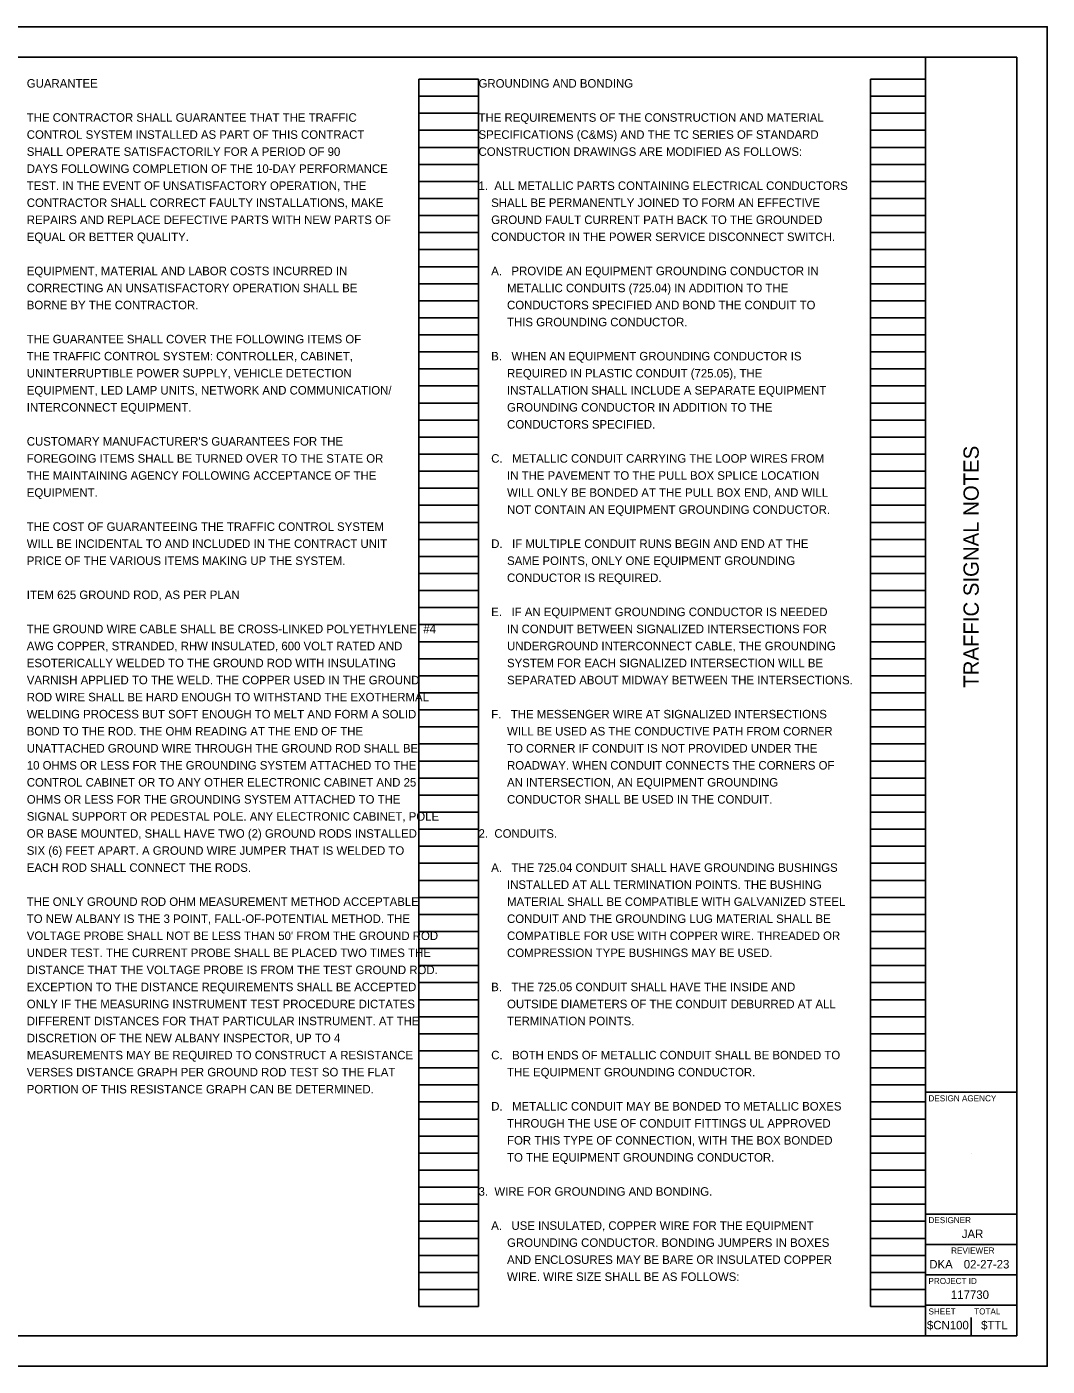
# Model space of a CAD drawing. Extents: x 0 to 34, y 0 to 22.
# Drawn here: x 17.24 to 34, y 0 to 22 of the extents above; entities that cross this region are included whole.
import ezdxf

# ---------------------------------------------------------------- set-up
doc = ezdxf.new("R2010")
doc.units = 0
for name, color, linetype in [('SH_Border', 7, 'Continuous'), ('SH_Cut_Line', 7, 'Continuous'), ('SH_Data', 7, 'Continuous'), ('SH_Text', 7, 'Continuous')]:
    doc.layers.add(name, color=color, linetype=linetype)

msp = doc.modelspace()

# ---------------------------------------------------------------- linework, layer by layer
at = {"layer": 'SH_Border'}
for p, q in [((32, 0.5), (32, 21.5)), ((32, 4.5), (33.5, 4.5)), ((32, 2.5), (33.5, 2.5)), ((32, 2), (33.5, 2)), ((32, 1.5), (33.5, 1.5)), ((32, 1), (33.5, 1))]:
    msp.add_line(p, q, dxfattribs=at)
msp.add_lwpolyline([(1.5, 21.5), (33.5, 21.5), (33.5, 0.5), (1.5, 0.5)], close=True, dxfattribs=at)
at = {"layer": 'SH_Cut_Line'}
msp.add_lwpolyline([(0, 0), (34, 0), (34, 22), (0, 22)], close=True, dxfattribs=at)
at = {"layer": 'SH_Data'}
for p, q in [((23.68, 0.98), (23.68, 21.14)), ((23.68, 21.14), (24.66, 21.14)), ((24.66, 0.98), (24.66, 21.14)), ((31.1, 0.98), (31.1, 21.14)), ((31.1, 21.14), (32, 21.14)), ((32, 0.98), (32, 21.14)), ((23.68, 20.86), (24.66, 20.86)), ((31.1, 20.86), (32, 20.86)), ((23.68, 20.58), (24.66, 20.58)), ((31.1, 20.58), (32, 20.58)), ((23.68, 20.3), (24.66, 20.3)), ((31.1, 20.3), (32, 20.3)), ((23.68, 20.02), (24.66, 20.02)), ((31.1, 20.02), (32, 20.02)), ((23.68, 19.74), (24.66, 19.74)), ((31.1, 19.74), (32, 19.74)), ((23.68, 19.46), (24.66, 19.46)), ((31.1, 19.46), (32, 19.46)), ((23.68, 19.18), (24.66, 19.18)), ((31.1, 19.18), (32, 19.18)), ((23.68, 18.9), (24.66, 18.9)), ((31.1, 18.9), (32, 18.9)), ((23.68, 18.62), (24.66, 18.62)), ((31.1, 18.62), (32, 18.62)), ((23.68, 18.34), (24.66, 18.34)), ((31.1, 18.34), (32, 18.34)), ((23.68, 18.06), (24.66, 18.06)), ((31.1, 18.06), (32, 18.06)), ((23.68, 17.78), (24.66, 17.78)), ((31.1, 17.78), (32, 17.78)), ((23.68, 17.5), (24.66, 17.5)), ((31.1, 17.5), (32, 17.5)), ((23.68, 17.22), (24.66, 17.22)), ((31.1, 17.22), (32, 17.22)), ((23.68, 16.94), (24.66, 16.94)), ((31.1, 16.94), (32, 16.94)), ((23.68, 16.66), (24.66, 16.66)), ((31.1, 16.66), (32, 16.66)), ((23.68, 16.38), (24.66, 16.38)), ((31.1, 16.38), (32, 16.38)), ((23.68, 16.1), (24.66, 16.1)), ((31.1, 16.1), (32, 16.1)), ((23.68, 15.82), (24.66, 15.82)), ((31.1, 15.82), (32, 15.82)), ((23.68, 15.54), (24.66, 15.54)), ((31.1, 15.54), (32, 15.54)), ((23.68, 15.26), (24.66, 15.26)), ((31.1, 15.26), (32, 15.26)), ((23.68, 14.98), (24.66, 14.98)), ((31.1, 14.98), (32, 14.98)), ((23.68, 14.7), (24.66, 14.7)), ((31.1, 14.7), (32, 14.7)), ((23.68, 14.42), (24.66, 14.42)), ((31.1, 14.42), (32, 14.42)), ((23.68, 14.14), (24.66, 14.14)), ((31.1, 14.14), (32, 14.14)), ((23.68, 13.86), (24.66, 13.86)), ((31.1, 13.86), (32, 13.86)), ((23.68, 13.58), (24.66, 13.58)), ((31.1, 13.58), (32, 13.58)), ((23.68, 13.3), (24.66, 13.3)), ((31.1, 13.3), (32, 13.3)), ((23.68, 13.02), (24.66, 13.02)), ((31.1, 13.02), (32, 13.02)), ((23.68, 12.74), (24.66, 12.74)), ((31.1, 12.74), (32, 12.74)), ((23.68, 12.46), (24.66, 12.46)), ((31.1, 12.46), (32, 12.46)), ((23.68, 12.18), (24.66, 12.18)), ((31.1, 12.18), (32, 12.18)), ((23.68, 11.9), (24.66, 11.9)), ((31.1, 11.9), (32, 11.9)), ((23.68, 11.62), (24.66, 11.62)), ((31.1, 11.62), (32, 11.62)), ((23.68, 11.34), (24.66, 11.34)), ((31.1, 11.34), (32, 11.34)), ((23.68, 11.06), (24.66, 11.06)), ((31.1, 11.06), (32, 11.06)), ((23.68, 10.78), (24.66, 10.78)), ((31.1, 10.78), (32, 10.78)), ((23.68, 10.5), (24.66, 10.5)), ((31.1, 10.5), (32, 10.5)), ((23.68, 10.22), (24.66, 10.22)), ((31.1, 10.22), (32, 10.22)), ((23.68, 9.94), (24.66, 9.94)), ((31.1, 9.94), (32, 9.94)), ((23.68, 9.66), (24.66, 9.66)), ((31.1, 9.66), (32, 9.66)), ((23.68, 9.38), (24.66, 9.38)), ((31.1, 9.38), (32, 9.38)), ((23.68, 9.1), (24.66, 9.1)), ((31.1, 9.1), (32, 9.1)), ((23.68, 8.82), (24.66, 8.82)), ((31.1, 8.82), (32, 8.82)), ((23.68, 8.54), (24.66, 8.54)), ((31.1, 8.54), (32, 8.54)), ((23.68, 8.26), (24.66, 8.26)), ((31.1, 8.26), (32, 8.26)), ((23.68, 7.98), (24.66, 7.98)), ((31.1, 7.98), (32, 7.98)), ((23.68, 7.7), (24.66, 7.7)), ((31.1, 7.7), (32, 7.7)), ((23.68, 7.42), (24.66, 7.42)), ((31.1, 7.42), (32, 7.42)), ((23.68, 7.14), (24.66, 7.14)), ((31.1, 7.14), (32, 7.14)), ((23.68, 6.86), (24.66, 6.86)), ((31.1, 6.86), (32, 6.86)), ((23.68, 6.58), (24.66, 6.58)), ((31.1, 6.58), (32, 6.58)), ((23.68, 6.3), (24.66, 6.3)), ((31.1, 6.3), (32, 6.3)), ((23.68, 6.02), (24.66, 6.02)), ((31.1, 6.02), (32, 6.02)), ((23.68, 5.74), (24.66, 5.74)), ((31.1, 5.74), (32, 5.74)), ((23.68, 5.46), (24.66, 5.46)), ((31.1, 5.46), (32, 5.46)), ((23.68, 5.18), (24.66, 5.18)), ((31.1, 5.18), (32, 5.18)), ((23.68, 4.9), (24.66, 4.9)), ((31.1, 4.9), (32, 4.9)), ((23.68, 4.62), (24.66, 4.62)), ((31.1, 4.62), (32, 4.62)), ((23.68, 4.34), (24.66, 4.34)), ((31.1, 4.34), (32, 4.34)), ((23.68, 4.06), (24.66, 4.06)), ((31.1, 4.06), (32, 4.06)), ((23.68, 3.78), (24.66, 3.78)), ((31.1, 3.78), (32, 3.78)), ((23.68, 3.5), (24.66, 3.5)), ((31.1, 3.5), (32, 3.5)), ((32.75, 3.5), (32.75, 3.5)), ((23.68, 3.22), (24.66, 3.22)), ((31.1, 3.22), (32, 3.22)), ((23.68, 2.94), (24.66, 2.94)), ((31.1, 2.94), (32, 2.94)), ((23.68, 2.66), (24.66, 2.66)), ((31.1, 2.66), (32, 2.66)), ((23.68, 2.38), (24.66, 2.38)), ((31.1, 2.38), (32, 2.38)), ((23.68, 2.1), (24.66, 2.1)), ((31.1, 2.1), (32, 2.1)), ((23.68, 1.82), (24.66, 1.82)), ((31.1, 1.82), (32, 1.82)), ((23.68, 1.54), (24.66, 1.54)), ((31.1, 1.54), (32, 1.54)), ((23.68, 1.26), (24.66, 1.26)), ((31.1, 1.26), (32, 1.26)), ((23.68, 0.98), (24.66, 0.98)), ((31.1, 0.98), (32, 0.98)), ((32.375, 0.675), (32.375, 0.675)), ((32.75, 0.5), (32.75, 0.8))]:
    msp.add_line(p, q, dxfattribs=at)

# ---------------------------------------------------------------- texts
msp.add_text('TRAFFIC SIGNAL NOTES', height=0.25, rotation=90, dxfattribs=at).set_placement((32.875, 11.144))
for s, height, p in [('DESIGN AGENCY', 0.1, (32.05, 4.35)), ('DESIGNER', 0.1, (32.05, 2.35)), ('JAR', 0.14, (32.597, 2.105)), ('REVIEWER', 0.1, (32.422, 1.85)), ('DKA', 0.14, (32.063, 1.605)), ('02-27-23', 0.14, (32.629, 1.605)), ('PROJECT ID', 0.1, (32.05, 1.35)), ('117730', 0.14, (32.419, 1.105)), ('SHEET', 0.1, (32.05, 0.85)), ('TOTAL', 0.1, (32.8, 0.85)), ('$CN100', 0.14, (32.025, 0.605)), ('$TTL', 0.14, (32.915, 0.605))]:
    msp.add_text(s, height=height, dxfattribs=at).set_placement(p)
at = {"layer": 'SH_Text'}
for s, p in [('GUARANTEE', (17.24, 21)), ('GROUNDING AND BONDING', (24.66, 21)), ('THE CONTRACTOR SHALL GUARANTEE THAT THE TRAFFIC', (17.24, 20.44)), ('THE REQUIREMENTS OF THE CONSTRUCTION AND MATERIAL', (24.66, 20.44)), ('CONTROL SYSTEM INSTALLED AS PART OF THIS CONTRACT', (17.24, 20.16)), ('SPECIFICATIONS (C&MS) AND THE TC SERIES OF STANDARD', (24.66, 20.16)), ('SHALL OPERATE SATISFACTORILY FOR A PERIOD OF 90', (17.24, 19.88)), ('CONSTRUCTION DRAWINGS ARE MODIFIED AS FOLLOWS:', (24.66, 19.88)), ('DAYS FOLLOWING COMPLETION OF THE 10-DAY PERFORMANCE', (17.24, 19.6)), ('TEST. IN THE EVENT OF UNSATISFACTORY OPERATION, THE', (17.24, 19.32)), ('1.  ALL METALLIC PARTS CONTAINING ELECTRICAL CONDUCTORS', (24.66, 19.32)), ('CONTRACTOR SHALL CORRECT FAULTY INSTALLATIONS, MAKE', (17.24, 19.04)), ('    SHALL BE PERMANENTLY JOINED TO FORM AN EFFECTIVE', (24.66, 19.04)), ('REPAIRS AND REPLACE DEFECTIVE PARTS WITH NEW PARTS OF', (17.24, 18.76)), ('    GROUND FAULT CURRENT PATH BACK TO THE GROUNDED', (24.66, 18.76)), ('EQUAL OR BETTER QUALITY.', (17.24, 18.48)), ('    CONDUCTOR IN THE POWER SERVICE DISCONNECT SWITCH.', (24.66, 18.48)), ('EQUIPMENT, MATERIAL AND LABOR COSTS INCURRED IN', (17.24, 17.92)), ('    A.   PROVIDE AN EQUIPMENT GROUNDING CONDUCTOR IN', (24.66, 17.92)), ('CORRECTING AN UNSATISFACTORY OPERATION SHALL BE', (17.24, 17.64)), ('         METALLIC CONDUITS (725.04) IN ADDITION TO THE', (24.66, 17.64)), ('BORNE BY THE CONTRACTOR.', (17.24, 17.36)), ('         CONDUCTORS SPECIFIED AND BOND THE CONDUIT TO', (24.66, 17.36)), ('         THIS GROUNDING CONDUCTOR.', (24.66, 17.08)), ('THE GUARANTEE SHALL COVER THE FOLLOWING ITEMS OF', (17.24, 16.8)), ('THE TRAFFIC CONTROL SYSTEM: CONTROLLER, CABINET,', (17.24, 16.52)), ('    B.   WHEN AN EQUIPMENT GROUNDING CONDUCTOR IS', (24.66, 16.52)), ('UNINTERRUPTIBLE POWER SUPPLY, VEHICLE DETECTION', (17.24, 16.24)), ('         REQUIRED IN PLASTIC CONDUIT (725.05), THE', (24.66, 16.24)), ('EQUIPMENT, LED LAMP UNITS, NETWORK AND COMMUNICATION/', (17.24, 15.96)), ('         INSTALLATION SHALL INCLUDE A SEPARATE EQUIPMENT', (24.66, 15.96)), ('INTERCONNECT EQUIPMENT.', (17.24, 15.68)), ('         GROUNDING CONDUCTOR IN ADDITION TO THE', (24.66, 15.68)), ('         CONDUCTORS SPECIFIED.', (24.66, 15.4)), ("CUSTOMARY MANUFACTURER'S GUARANTEES FOR THE", (17.24, 15.12)), ('FOREGOING ITEMS SHALL BE TURNED OVER TO THE STATE OR', (17.24, 14.84)), ('    C.   METALLIC CONDUIT CARRYING THE LOOP WIRES FROM', (24.66, 14.84)), ('THE MAINTAINING AGENCY FOLLOWING ACCEPTANCE OF THE', (17.24, 14.56)), ('         IN THE PAVEMENT TO THE PULL BOX SPLICE LOCATION', (24.66, 14.56)), ('EQUIPMENT.', (17.24, 14.28)), ('         WILL ONLY BE BONDED AT THE PULL BOX END, AND WILL', (24.66, 14.28)), ('         NOT CONTAIN AN EQUIPMENT GROUNDING CONDUCTOR.', (24.66, 14)), ('THE COST OF GUARANTEEING THE TRAFFIC CONTROL SYSTEM', (17.24, 13.72)), ('WILL BE INCIDENTAL TO AND INCLUDED IN THE CONTRACT UNIT', (17.24, 13.44)), ('    D.   IF MULTIPLE CONDUIT RUNS BEGIN AND END AT THE', (24.66, 13.44)), ('PRICE OF THE VARIOUS ITEMS MAKING UP THE SYSTEM.', (17.24, 13.16)), ('         SAME POINTS, ONLY ONE EQUIPMENT GROUNDING', (24.66, 13.16)), ('         CONDUCTOR IS REQUIRED.', (24.66, 12.88)), ('ITEM 625 GROUND ROD, AS PER PLAN', (17.24, 12.6)), ('    E.   IF AN EQUIPMENT GROUNDING CONDUCTOR IS NEEDED', (24.66, 12.32)), ('THE GROUND WIRE CABLE SHALL BE CROSS-LINKED POLYETHYLENE, #4 ', (17.24, 12.04)), ('         IN CONDUIT BETWEEN SIGNALIZED INTERSECTIONS FOR', (24.66, 12.04)), ('AWG COPPER, STRANDED, RHW INSULATED, 600 VOLT RATED AND ', (17.24, 11.76)), ('         UNDERGROUND INTERCONNECT CABLE, THE GROUNDING', (24.66, 11.76)), ('ESOTERICALLY WELDED TO THE GROUND ROD WITH INSULATING ', (17.24, 11.48)), ('         SYSTEM FOR EACH SIGNALIZED INTERSECTION WILL BE', (24.66, 11.48)), ('VARNISH APPLIED TO THE WELD. THE COPPER USED IN THE GROUND ', (17.24, 11.2)), ('         SEPARATED ABOUT MIDWAY BETWEEN THE INTERSECTIONS.', (24.66, 11.2)), ('ROD WIRE SHALL BE HARD ENOUGH TO WITHSTAND THE EXOTHERMAL ', (17.24, 10.92)), ('WELDING PROCESS BUT SOFT ENOUGH TO MELT AND FORM A SOLID ', (17.24, 10.64)), ('    F.   THE MESSENGER WIRE AT SIGNALIZED INTERSECTIONS', (24.66, 10.64)), ('BOND TO THE ROD. THE OHM READING AT THE END OF THE ', (17.24, 10.36)), ('         WILL BE USED AS THE CONDUCTIVE PATH FROM CORNER', (24.66, 10.36)), ('UNATTACHED GROUND WIRE THROUGH THE GROUND ROD SHALL BE ', (17.24, 10.08)), ('         TO CORNER IF CONDUIT IS NOT PROVIDED UNDER THE', (24.66, 10.08)), ('10 OHMS OR LESS FOR THE GROUNDING SYSTEM ATTACHED TO THE ', (17.24, 9.8)), ('         ROADWAY. WHEN CONDUIT CONNECTS THE CORNERS OF', (24.66, 9.8)), ('CONTROL CABINET OR TO ANY OTHER ELECTRONIC CABINET AND 25 ', (17.24, 9.52)), ('         AN INTERSECTION, AN EQUIPMENT GROUNDING', (24.66, 9.52)), ('OHMS OR LESS FOR THE GROUNDING SYSTEM ATTACHED TO THE ', (17.24, 9.24)), ('         CONDUCTOR SHALL BE USED IN THE CONDUIT.', (24.66, 9.24)), ('SIGNAL SUPPORT OR PEDESTAL POLE. ANY ELECTRONIC CABINET, POLE ', (17.24, 8.96)), ('OR BASE MOUNTED, SHALL HAVE TWO (2) GROUND RODS INSTALLED ', (17.24, 8.68)), ('2.  CONDUITS.', (24.66, 8.68)), ('SIX (6) FEET APART. A GROUND WIRE JUMPER THAT IS WELDED TO ', (17.24, 8.4)), ('EACH ROD SHALL CONNECT THE RODS.', (17.24, 8.12)), ('    A.   THE 725.04 CONDUIT SHALL HAVE GROUNDING BUSHINGS', (24.66, 8.12)), ('         INSTALLED AT ALL TERMINATION POINTS. THE BUSHING', (24.66, 7.84)), ('THE ONLY GROUND ROD OHM MEASUREMENT METHOD ACCEPTABLE ', (17.24, 7.56)), ('         MATERIAL SHALL BE COMPATIBLE WITH GALVANIZED STEEL', (24.66, 7.56)), ('TO NEW ALBANY IS THE 3 POINT, FALL-OF-POTENTIAL METHOD. THE ', (17.24, 7.28)), ('         CONDUIT AND THE GROUNDING LUG MATERIAL SHALL BE', (24.66, 7.28)), ("VOLTAGE PROBE SHALL NOT BE LESS THAN 50' FROM THE GROUND ROD ", (17.24, 7)), ('         COMPATIBLE FOR USE WITH COPPER WIRE. THREADED OR', (24.66, 7)), ('UNDER TEST. THE CURRENT PROBE SHALL BE PLACED TWO TIMES THE ', (17.24, 6.72)), ('         COMPRESSION TYPE BUSHINGS MAY BE USED.', (24.66, 6.72)), ('DISTANCE THAT THE VOLTAGE PROBE IS FROM THE TEST GROUND ROD. ', (17.24, 6.44)), ('EXCEPTION TO THE DISTANCE REQUIREMENTS SHALL BE ACCEPTED ', (17.24, 6.16)), ('    B.   THE 725.05 CONDUIT SHALL HAVE THE INSIDE AND', (24.66, 6.16)), ('ONLY IF THE MEASURING INSTRUMENT TEST PROCEDURE DICTATES ', (17.24, 5.88)), ('         OUTSIDE DIAMETERS OF THE CONDUIT DEBURRED AT ALL', (24.66, 5.88)), ('DIFFERENT DISTANCES FOR THAT PARTICULAR INSTRUMENT. AT THE ', (17.24, 5.6)), ('         TERMINATION POINTS.', (24.66, 5.6)), ('DISCRETION OF THE NEW ALBANY INSPECTOR, UP TO 4 ', (17.24, 5.32)), ('MEASUREMENTS MAY BE REQUIRED TO CONSTRUCT A RESISTANCE ', (17.24, 5.04)), ('    C.   BOTH ENDS OF METALLIC CONDUIT SHALL BE BONDED TO', (24.66, 5.04)), ('VERSES DISTANCE GRAPH PER GROUND ROD TEST SO THE FLAT ', (17.24, 4.76)), ('         THE EQUIPMENT GROUNDING CONDUCTOR.', (24.66, 4.76)), ('PORTION OF THIS RESISTANCE GRAPH CAN BE DETERMINED.', (17.24, 4.48)), ('    D.   METALLIC CONDUIT MAY BE BONDED TO METALLIC BOXES', (24.66, 4.2)), ('         THROUGH THE USE OF CONDUIT FITTINGS UL APPROVED', (24.66, 3.92)), ('         FOR THIS TYPE OF CONNECTION, WITH THE BOX BONDED', (24.66, 3.64)), ('         TO THE EQUIPMENT GROUNDING CONDUCTOR.', (24.66, 3.36)), ('3.  WIRE FOR GROUNDING AND BONDING.', (24.66, 2.8)), ('    A.   USE INSULATED, COPPER WIRE FOR THE EQUIPMENT', (24.66, 2.24)), ('         GROUNDING CONDUCTOR. BONDING JUMPERS IN BOXES', (24.66, 1.96)), ('         AND ENCLOSURES MAY BE BARE OR INSULATED COPPER', (24.66, 1.68)), ('         WIRE. WIRE SIZE SHALL BE AS FOLLOWS:', (24.66, 1.4))]:
    msp.add_text(s, height=0.14, dxfattribs=at).set_placement(p)

doc.saveas('drawing.dxf')
